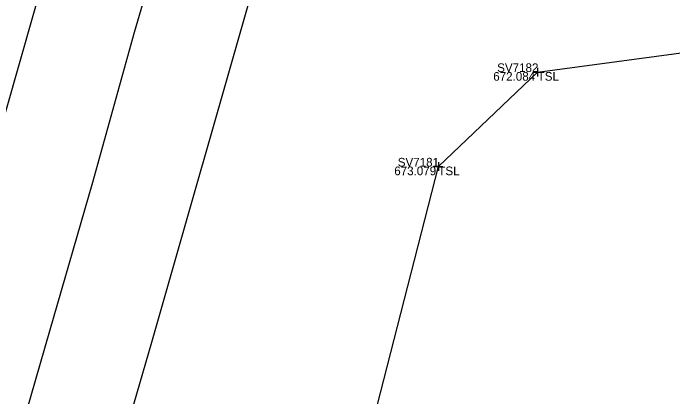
# Model space of a CAD drawing. Extents: x 1659932 to 1663108, y 619867 to 620611.
# Drawn here: x 1661449.7 to 1661525.8, y 620261 to 620305.2 of the extents above; entities that cross this region are included whole.
import ezdxf

# ---------------------------------------------------------------- set-up
doc = ezdxf.new("R2010")
doc.units = 0
for name, color, linetype in [('PM_X_Edge_Line', 7, 'Continuous'), ('PM_X_Lane_Line', 7, 'Continuous'), ('PV_X_EOP', 7, 'Continuous'), ('SV_X_Shot_Marker', 7, 'Continuous'), ('SV_X_Text_Comment', 7, 'Continuous'), ('SV_X_Text_Elevation', 7, 'Continuous'), ('SV_X_Text_Name', 7, 'Continuous'), ('SV_X_Toe_of_Slope', 7, 'Continuous')]:
    doc.layers.add(name, color=color, linetype=linetype)

msp = doc.modelspace()

# ---------------------------------------------------------------- linework, layer by layer
at = {"layer": 'PM_X_Edge_Line'}
msp.add_lwpolyline([(1661533.637, 620545.425), (1661528.108, 620526.358), (1661523.208, 620509.615), (1661518.012, 620491.429), (1661511.994, 620470.167), (1661507.322, 620453.725), (1661502.995, 620438.636), (1661498.703, 620424.135), (1661495.255, 620412.323), (1661490.204, 620394.571), (1661483.245, 620370.315), (1661475.775, 620344.717), (1661468.35, 620318.812), (1661463.705, 620302.949), (1661458.897, 620285.652), (1661453.934, 620268.511), (1661449.632, 620253.601), (1661448.095, 620248.463)], dxfattribs=at)
at = {"layer": 'PM_X_Lane_Line'}
msp.add_lwpolyline([(1661525.681, 620560.345), (1661514.724, 620522.512), (1661503.087, 620483.055), (1661491.598, 620443.157), (1661480.26, 620403.462), (1661469.087, 620364.672), (1661458.332, 620327.003), (1661447.315, 620288.523), (1661436.528, 620250.631)], dxfattribs=at)
at = {"layer": 'PV_X_EOP'}
msp.add_lwpolyline([(1661460.209, 620248.191), (1661465.734, 620267.256), (1661477.474, 620308.258), (1661484.14, 620332.148), (1661489.977, 620352.146), (1661493.172, 620362.868), (1661496.766, 620375.458), (1661502.254, 620394.508), (1661508.039, 620414.587), (1661512.58, 620430.248), (1661515.801, 620441.463), (1661520.55, 620457.989), (1661522.894, 620466.1), (1661527.537, 620482.075), (1661533.623, 620503.392), (1661537.444, 620516.811), (1661543.134, 620536.578)], dxfattribs=at)
at = {"layer": 'SV_X_Shot_Marker'}
for p, q in [((1661510.242, 620298.878), (1661510.242, 620297.878)), ((1661509.742, 620298.378), (1661510.742, 620298.378)), ((1661510.242, 620298.378), (1661510.242, 620298.378)), ((1661498.786, 620287.984), (1661498.786, 620286.984)), ((1661498.286, 620287.484), (1661499.286, 620287.484)), ((1661498.786, 620287.484), (1661498.786, 620287.484))]:
    msp.add_line(p, q, dxfattribs=at)
at = {"layer": 'SV_X_Toe_of_Slope'}
msp.add_lwpolyline([(1661490.605, 620170.614), (1661477.149, 620203.096), (1661498.786, 620287.484), (1661510.242, 620298.378), (1661539.687, 620302.32)], dxfattribs=at)

# ---------------------------------------------------------------- texts
at = {"layer": 'SV_X_Text_Comment'}
for p in [(1661510.242, 620297.378), (1661498.786, 620286.484)]:
    msp.add_text('TSL', height=1, dxfattribs=at).set_placement(p)
at = {"layer": 'SV_X_Text_Elevation'}
for s, p in [('672.084', (1661505.12, 620297.378)), ('673.079', (1661493.702, 620286.484))]:
    msp.add_text(s, height=1, dxfattribs=at).set_placement(p)
at = {"layer": 'SV_X_Text_Name'}
for s, p in [('SV7182', (1661505.571, 620298.378)), ('SV7181', (1661494.106, 620287.484))]:
    msp.add_text(s, height=1, dxfattribs=at).set_placement(p)

doc.saveas('drawing.dxf')
